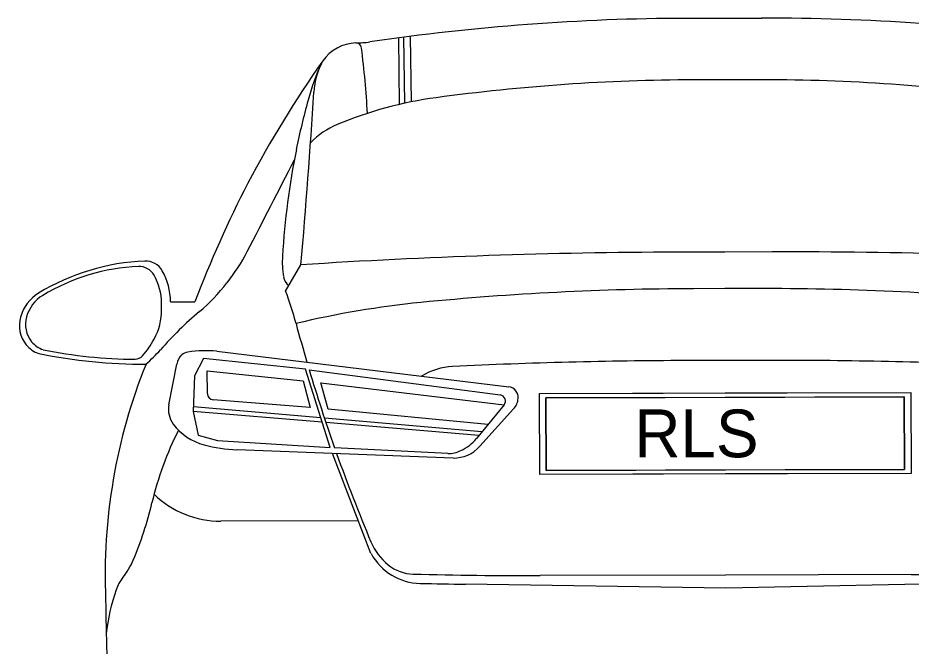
# Model space of a CAD drawing. Extents: x 10133 to 81668, y 4692 to 11018.
# Drawn here: x 29266.5 to 29371.5, y 6033.8 to 6107.6 of the extents above; entities that cross this region are included whole.
import ezdxf

# ---------------------------------------------------------------- set-up
doc = ezdxf.new("R2010")
doc.units = 0
doc.layers.add('Cell', color=7, linetype='Continuous')
doc.layers.add('SheetBorder', color=7, linetype='Continuous')

msp = doc.modelspace()

# ---------------------------------------------------------------- linework, layer by layer
at = {"layer": 'Cell'}
for p, q in [((29311.38, 6097.47), (29311.28, 6105.29)), ((29311.99, 6097.6), (29311.88, 6105.37)), ((29312.77, 6097.77), (29312.66, 6105.47)), ((29297.98, 6075.55), (29299.78, 6078.63)), ((29283.4, 6073.37), (29283.4, 6074.13)), ((29284.46, 6074.29), (29287.32, 6074.29)), ((29289.9, 6068.49), (29324.24, 6064.31)), ((29284.27, 6062.19), (29285.19, 6066.96)), ((29300.75, 6066.31), (29323.22, 6063.34)), ((29327.83, 6063.52), (29349.66, 6063.57)), ((29327.86, 6054.01), (29327.83, 6063.52)), ((29349.66, 6063.57), (29371.5, 6063.63)), ((29371.5, 6063.63), (29371.53, 6054.13)), ((29300.88, 6061.87), (29289.45, 6062.76)), ((29349.67, 6063.05), (29328.6, 6063)), ((29328.6, 6063), (29328.63, 6054.48)), ((29370.73, 6063.11), (29349.67, 6063.05)), ((29370.76, 6054.59), (29370.73, 6063.11)), ((29302.28, 6060.13), (29287.13, 6061.39)), ((29302.12, 6060.65), (29287.15, 6061.94)), ((29323.67, 6062.16), (29320.42, 6058.23)), ((29324.79, 6061.7), (29320.82, 6057.31)), ((29321.07, 6059.01), (29302.55, 6060.61)), ((29320.72, 6058.59), (29302.73, 6060.09)), ((29317.68, 6055.93), (29292.27, 6056.9)), ((29308.02, 6044.72), (29303.49, 6056.47)), ((29317.04, 6056.45), (29303.74, 6057.14)), ((29349.7, 6054.07), (29327.86, 6054.01)), ((29328.63, 6054.48), (29349.69, 6054.54)), ((29349.69, 6054.54), (29370.76, 6054.59)), ((29371.53, 6054.13), (29349.7, 6054.07)), ((29306.55, 6048.55), (29290.38, 6048.51))]:
    msp.add_line(p, q, dxfattribs=at)
for points in [[(29345.09, 6107.59), (29349.52, 6107.6), (29353.96, 6107.61)], [(29353.1, 6100.38), (29349.55, 6100.37), (29345.99, 6100.36)], [(29355.21, 6080.14), (29349.61, 6080.12), (29344.01, 6080.11)], [(29353.31, 6075.84), (29349.63, 6075.83), (29345.94, 6075.82)], [(29303.21, 6057.16), (29300.32, 6066.37), (29288.33, 6067.63), (29287.28, 6065.58), (29287.13, 6061.39), (29287.7, 6058.62), (29289.97, 6057.97), (29303.21, 6057.16)], [(29354.31, 6067.4), (29349.65, 6067.38), (29345, 6067.37)], [(29288.79, 6063.47), (29288.78, 6066.17), (29300.03, 6065), (29300.88, 6061.87)], [(29321.77, 6059.87), (29302.98, 6061.67), (29302.11, 6064.75), (29323.67, 6062.16)], [(29371.53, 6042.23), (29349.73, 6042.18), (29327.93, 6042.12)], [(29380.35, 6041.26), (29349.74, 6040.64), (29319.12, 6041.1)]]:
    msp.add_lwpolyline(points, dxfattribs=at)
for centre, major_axis, start_param, end_param in [((29354.82, 5839.96), (6.56, -267.57), 2.978516, 3.120007), ((29345.95, 5839.94), (6.56, -267.57), 3.120007, 3.261498), ((29306.46, 6099.55), (0.13, -5.16), 3.157374, 4.057603), ((29306.35, 6115.46), (0.26, -10.75), 6.249039, 6.40309), ((29306.24, 6104.02), (0.017, -0.688), 1.669997, 3.09954), ((29189.39, 6089.32), (2.94, -120.09), 1.605795, 1.669997), ((29405.26, 6027.72), (3.15, -128.37), 4.065719, 4.19748), ((29309.95, 6098.37), (0.22, -8.78), 4.186925, 4.6247), ((29328.43, 6090.05), (0.72, -29.28), 4.260033, 4.414465), ((29346.75, 5865.26), (5.76, -235.03), 3.120007, 3.251156), ((29353.86, 5865.28), (5.76, -235.03), 2.988858, 3.120007), ((28556.58, 6146.98), (18.54, -756.63), 1.456201, 1.483107), ((29322.05, 6050.5), (1.18, -48.18), 3.251156, 3.505182), ((29380.53, 6075.21), (2.06, -84.14), 4.414465, 4.485126), ((29307.58, 6086.39), (0.23, -9.42), 3.505182, 3.916515), ((29385.06, 6074.26), (2.18, -88.82), 4.485126, 4.62747), ((27427.51, 7075.87), (52.38, -2137.28), 1.062183, 1.067867), ((29414.73, 6024), (3.4, -138.6), 4.20651, 4.317037), ((29272.89, 6091.17), (0.58, -23.57), 0.875095, 1.062183), ((29308.66, 6078.98), (0.27, -11.22), 4.62747, 4.84388), ((29346.39, 5343), (18.06, -736.9), 3.120007, 3.180922), ((29357.58, 5343.03), (18.06, -736.9), 3.059092, 3.120007), ((29282.47, 6052.39), (0.65, -26.69), 3.156071, 3.657252), ((29281.62, 6054.42), (0.59, -24.02), 3.156071, 3.657252), ((29280.77, 6076.37), (0.05, -2.06), 2.074046, 3.156071), ((29281.53, 6076.78), (0.06, -2.29), 2.074046, 3.156071), ((29276.94, 6074.11), (0.16, -6.55), 1.549211, 2.074046), ((29277.27, 6074.27), (0.18, -7.28), 1.549211, 2.074046), ((29299.27, 6077.48), (0.04, -1.58), 4.84388, 5.634844), ((29273.35, 6090.79), (0.56, -22.96), 0.669636, 0.875095), ((29271.36, 6071.18), (0.12, -4.79), 3.657252, 4.409317), ((29258.82, 6060.55), (1.04, -42.46), 1.813063, 1.907743), ((29347.05, 5730.07), (8.47, -345.65), 3.120007, 3.214195), ((29354.43, 5730.09), (8.47, -345.65), 3.025819, 3.120007), ((29271.61, 6071.34), (0.11, -4.31), 3.657252, 4.409317), ((29324.49, 5964.15), (2.71, -110.54), 3.214195, 3.350783), ((29276.33, 6073.36), (0.18, -7.17), 1.044575, 1.549211), ((29315.42, 6039.54), (1.07, -43.68), 3.811229, 3.959395), ((29270.22, 6071.51), (0.09, -3.59), 4.409317, 5.371388), ((29270.59, 6071.63), (0.08, -3.23), 4.409317, 5.371388), ((29488.81, 6124.22), (4.88, -199.32), 4.954656, 4.978285), ((29273.32, 6075.03), (0.26, -10.65), 0.81856, 1.044575), ((29269.95, 6071.28), (0.08, -3.23), 5.371388, 5.949523), ((29270.34, 6071.43), (0.07, -2.9), 5.371388, 5.949523), ((29281.19, 6129.55), (1.53, -62.57), 6.059144, 6.264389), ((29280.46, 6123.86), (1.38, -56.31), 6.059144, 6.255117), ((29280.29, 6068.74), (0.03, -1.2), 6.255117, 7.101746), ((29271.05, 6079.69), (0.41, -16.59), 0.67276, 0.817803), ((29287.18, 6066.56), (0.05, -2.06), 3.889677, 4.49328), ((29286.66, 6067.05), (0.03, -1.34), 3.246567, 3.860069), ((29288.68, 6052.91), (0.38, -15.62), 3.037393, 3.25952), ((29341.34, 6042.12), (1.6, -65.48), 4.299233, 4.731757), ((29318, 6058.7), (0.2, -7.98), 3.16484, 3.655389), ((29346.99, 5447.69), (15.18, -619.51), 3.120007, 3.16484), ((29356.3, 5447.71), (15.18, -619.51), 3.075174, 3.120007), ((29488.81, 6124.22), (4.88, -199.32), 4.982915, 5.031395), ((29324.09, 6063.05), (0.03, -1.26), 1.452565, 2.998081), ((29289.5, 6063.48), (0.018, -0.717), 4.690803, 6.182772), ((29323.13, 6062.63), (0.018, -0.717), 0.848084, 2.98756), ((29323.25, 6063.13), (0.05, -2.12), 0.803712, 1.452565), ((29286.96, 6061.62), (0.07, -2.79), 4.482074, 5.341112), ((29290.1, 6064.06), (0.17, -6.8), 5.341112, 6.001372), ((29319.01, 6041.66), (0.94, -38.33), 4.212642, 4.451141), ((29292.93, 6074.99), (0.44, -18.1), 6.001372, 6.221435), ((29317.73, 6060.19), (0.1, -4.26), 6.247367, 7.087411), ((29316.32, 6061.73), (0.13, -5.44), 0.413202, 0.848084), ((29488.81, 6124.22), (4.88, -199.32), 5.035037, 5.091004), ((29317.02, 6060.21), (0.09, -3.76), 6.265072, 6.696387), ((29290.34, 6060.09), (0.28, -11.58), 5.503194, 6.2616), ((29240.9, 6060.8), (1.06, -43.14), 1.144973, 1.309548), ((29314.24, 6048.76), (0.17, -6.86), 5.091004, 5.589773), ((29313.94, 6048.07), (0.17, -6.87), 5.197336, 6.238997), ((29272.44, 6047.22), (0.21, -8.4), 0.858001, 1.144973), ((29313.13, 6047.33), (0.12, -5.04), 5.589773, 6.233227), ((29369.82, 6576.04), (13.08, -533.65), 6.2616, 6.289972), ((29282.38, 6038.93), (0.11, -4.64), 3.999593, 4.355149), ((29326.21, 6575.92), (13.08, -533.65), 6.233227, 6.2616), ((29300.82, 6032.46), (0.6, -24.42), 4.355149, 4.573388), ((29333.4, 7068.62), (25.18, -1027.33), 6.238997, 6.244243), ((29521.88, 6041.67), (6.09, -248.5), 4.697896, 4.748689)]:
    msp.add_ellipse(centre, major_axis=major_axis, ratio=0.985916, start_param=start_param, end_param=end_param, dxfattribs=at)
at = {"layer": 'SheetBorder'}
for points in [[(29327.83, 6063.52), (29371.5, 6063.63), (29371.53, 6054.13), (29327.86, 6054.01)], [(29328.6, 6063), (29370.73, 6063.11), (29370.76, 6054.59), (29328.63, 6054.48)]]:
    msp.add_lwpolyline(points, close=True, dxfattribs=at)

# ---------------------------------------------------------------- texts
msp.add_text('RLS', height=5.612, rotation=359.9242, dxfattribs=at).set_placement((29338.99, 6056.03))

doc.saveas('drawing.dxf')
